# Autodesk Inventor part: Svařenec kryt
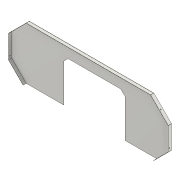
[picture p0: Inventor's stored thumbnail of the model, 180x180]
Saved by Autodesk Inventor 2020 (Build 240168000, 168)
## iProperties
Created: 2025-04
Part Number: Svařenec kryt
Material: Ocel
Document SubType Name: Modeling
Designer: doma
Density: 7.85 g/cm^3
Appearance: Ocel
Mass: 2680.45 g
Surface Area: 5732.74 cm^2
Volume: 341.459 cm^3
Author: doma
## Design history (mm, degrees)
sketch "Náčrt1"
  geometry: L1 (1513.721, 322.322)-(1513.721, 397.322); L2 (1513.721, 322.322)-(1513.721, 247.322); L3 (2563.721, 322.322)-(2563.721, 397.322); L4 (2563.721, 322.322)-(2563.721, 247.322); L5 (1663.721, 152.322)-(1608.721, 152.322); L6 (1663.721, 152.322)-(1853.721, 152.322); L7 (2263.721, 152.322)-(2468.721, 152.322); L8 (2263.721, 322.322)-(2263.721, 255.322); L9 (2233.721, 432.322)-(1883.721, 432.322); L10 (2263.721, 402.322)-(2233.721, 432.322); L11 (2263.721, 322.322)-(2263.721, 402.322); L12 (1853.721, 322.322)-(1853.721, 402.322); L13 (1883.721, 432.322)-(1853.721, 402.322); L14 (1853.721, 322.322)-(1853.721, 152.322); L15 (1513.721, 397.322)-(1628.721, 512.322); L16 (2563.721, 397.322)-(2448.721, 512.322); L17 (1513.721, 247.322)-(1608.721, 152.322); L18 (2563.721, 247.322)-(2468.721, 152.322); L19 (2058.721, 512.322)-(1628.721, 512.322); L20 (2058.721, 512.322)-(2448.721, 512.322); L21 (2263.721, 255.322)-(2263.721, 152.322); L22 (2058.721, 514.322)-(2448.721, 514.322); L23 (2565.135, 398.736)-(2450.135, 513.736); L24 (2565.721, 322.322)-(2565.721, 397.322); L25 (2565.721, 322.322)-(2565.721, 247.322); L26 (2565.135, 245.908)-(2470.135, 150.908); L27 (2263.721, 150.322)-(2468.721, 150.322); L28 (2261.721, 255.322)-(2261.721, 152.322); L29 (2261.721, 322.322)-(2261.721, 255.322); L30 (2261.721, 322.322)-(2261.721, 402.322); L31 (2262.307, 400.908)-(2232.307, 430.908); L32 (2233.721, 430.322)-(1883.721, 430.322); L33 (1885.135, 430.908)-(1855.135, 400.908); L34 (1855.721, 322.322)-(1855.721, 402.322); L35 (1855.721, 322.322)-(1855.721, 152.322); L36 (1663.721, 150.322)-(1853.721, 150.322); L37 (1663.721, 150.322)-(1608.721, 150.322); L38 (1512.307, 245.908)-(1607.307, 150.908); L39 (1511.721, 322.322)-(1511.721, 247.322); L40 (1511.721, 322.322)-(1511.721, 397.322); L41 (1512.307, 398.736)-(1627.307, 513.736); L42 (2058.721, 514.322)-(1628.721, 514.322); L43 (2263.721, 150.322)-(2261.721, 150.322); L44 (2261.721, 150.322)-(2261.721, 152.322); L45 (2470.135, 150.908)-(2469.549, 150.322); L46 (1607.307, 150.908)-(1607.893, 150.322); L47 (1607.893, 150.322)-(1608.721, 150.322); L48 (1853.721, 150.322)-(1855.721, 150.322); L49 (1855.721, 150.322)-(1855.721, 152.322); L50 (1631.284, 519.411)-(1626.458, 514.585); L51 (1626.458, 514.585)-(1511.458, 399.585); L52 (1511.458, 399.585)-(1508.966, 397.092); L53 (1510.521, 322.322)-(1510.521, 397.322); L54 (1510.521, 397.322)-(1510.521, 401.607); L55 (1510.521, 322.322)-(1510.521, 247.322); L56 (1510.521, 247.322)-(1510.521, 242.989); L57 (1507.769, 248.748)-(1511.458, 245.059); L58 (1511.458, 245.059)-(1606.458, 150.059); L59 (1606.458, 150.059)-(1607.044, 149.473); L60 (1607.044, 149.473)-(1607.893, 150.322); L61 (1512.307, 245.908)-(1511.721, 246.494); L62 (1510.521, 247.694)-(1508.618, 249.597); L63 (1511.721, 247.322)-(1511.721, 246.494); L64 (1511.721, 244.796)-(1511.721, 242.989)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; 21 further points
  constraints: 200 end point, 21 parallel, 14 point on line, 8 vertical, 6 horizontal, 3 perpendicular, 1 collinear, 1 other
  dimensions: "d54" = 2 distance between parallel lines of L20 L22; "d55" = 2 distance between parallel lines of L16 L23; "d56" = 2 distance between parallel lines of L3 L24; "d57" = 2 distance between parallel lines of L4 L25; "d58" = 2 distance between parallel lines of L18 L26; "d59" = 2 distance between parallel lines of L7 L27; "d60" = 2 distance between parallel lines of L21 L28; "d61" = 2 distance between parallel lines of L8 L29; "d62" = 2 distance between parallel lines of L11 L30; "d63" = 2 distance between parallel lines of L10 L31; "d64" = 2 distance between parallel lines of L9 L32; "d65" = 2 distance between parallel lines of L13 L33; "d66" = 2 distance between parallel lines of L12 L34; "d67" = 2 distance between parallel lines of L14 L35; "d68" = 2 distance between parallel lines of L6 L36; "d69" = 2 distance between parallel lines of L5 L37; "d70" = 2 distance between parallel lines of L17 L38; "d71" = 2 distance between parallel lines of L2 L39; "d72" = 2 distance between parallel lines of L1 L40; "d73" = 2 distance between parallel lines of L15 L41; "d74" = 2 distance between parallel lines of L19 L42; "d75" = 1.2 distance between parallel lines of L41 L51; "d76" = 1.2 distance between parallel lines of L40 L53; "d77" = 1.2 distance between parallel lines of L39 L55; "d78" = 1.2 distance between parallel lines of L38 L58; "d79" = 1.2 distance between parallel lines of L42 L69; "d80" = 1.2 distance between parallel lines of L22 L71; "d81" = 1.2 distance between parallel lines of L23 L78; "d82" = 1.2 distance between parallel lines of L24 L80; "d83" = 1.2 distance between parallel lines of L25 L82; "d84" = 1.2 distance between parallel lines of L26 L85
extrude "Vysunutí1" new body sketch "Náčrt1" distance "d85" = 21.2; taper "d86" = 0 deg
extrude "Vysunutí2" join sketch "Náčrt1" distance "d87" = 1.2; taper "d88" = 0 deg
sketch "Náčrt2"
  geometry: L1 (-165.286, 21.2)-(0, 21.2) reference; L2 (-165.286, 13.2)-(0, 13.2); C1 r 2.75 at (-82.643, 13.2); 1 further point
  constraints: 2 end point, 1 centre point, 1 midpoint, 1 parallel
  dimensions: "d89" = 8 distance between parallel lines of L1 L2; "d90" = 5.5 diameter of C1
extrude "Vysunutí3" cut sketch "Náčrt2" distance "d91" = 1.2; taper "d92" = 0 deg
sketch "Náčrt3"
  geometry: L1 (-165.286, 21.2)-(0, 21.2) reference; L2 (-165.286, 13.2)-(0, 13.2); C1 r 2.75 at (-82.643, 13.2); 1 further point
  constraints: 2 end point, 1 centre point, 1 midpoint, 1 parallel
  dimensions: "d93" = 8 distance between parallel lines of L1 L2; "d94" = 5.5 diameter of C1
extrude "Vysunutí4" cut sketch "Náčrt3" distance "d95" = 1.2; taper "d96" = 0 deg
sketch "Náčrt4"
  geometry: L1 (21.2, 152.651)-(21.2, 0) reference; L2 (13.2, 152.651)-(13.2, 0); C1 r 2.75 at (13.2, 20); 1 further point
  constraints: 2 end point, 1 centre point, 1 parallel, 1 point on line
  dimensions: "d97" = 8 distance between parallel lines of L1 L2; "d98" = 5.5 diameter of C1; "d99" = 20 vertical distance of L1.end C1.centre
extrude "Vysunutí5" cut sketch "Náčrt4" extent not by distance; stored distance "d100" = 0; taper "d101" = 0 deg
sketch "Náčrt5"
  geometry: L1 (-1627.893, 514.322)-(-2449.549, 514.322) reference; L2 (-1627.893, 514.322)-(-1627.893, 515.522); L3 (-2450.047, 515.522)-(-1627.396, 515.522) reference; L4 (-1627.893, 514.322)-(-1627.044, 515.171); L5 (-1627.396, 515.522)-(-1510.521, 398.647) reference; L6 (-1628.721, 515.522)-(-1624.975, 515.522) reference; L7 (-1631.284, 519.411)-(-1626.458, 514.585) reference; L8 (-1511.721, 398.15)-(-1627.893, 514.322) reference; L9 (-1511.721, 398.15)-(-1510.873, 398.999); L10 (-1511.721, 398.15)-(-1510.521, 398.15); L11 (-1510.521, 398.647)-(-1510.521, 245.996) reference; L12 (-1511.458, 399.585)-(-1508.966, 397.092) reference; L13 (-1510.521, 397.322)-(-1510.521, 401.607) reference; L14 (-1510.521, 247.322)-(-1510.521, 242.989) reference; L15 (-1507.769, 248.748)-(-1511.458, 245.059) reference; L16 (-1511.721, 246.494)-(-1511.721, 398.15) reference; L17 (-1511.721, 246.494)-(-1510.521, 246.494); L18 (-1511.721, 246.494)-(-1510.873, 245.645); L19 (-1510.521, 245.996)-(-1607.044, 149.473) reference; L20 (-1510.521, 245.996)-(-1607.044, 149.473) reference; L21 (-2448.721, 515.522)-(-2452.625, 515.522) reference; L22 (-2448.73, 516.839)-(-2450.984, 514.585) reference; L23 (-2449.549, 514.322)-(-2449.549, 515.522); L24 (-2449.549, 514.322)-(-2450.398, 515.171); L25 (-2565.984, 399.585)-(-2570.969, 394.6) reference; L26 (-2566.921, 397.322)-(-2566.921, 403.132) reference; L27 (-2565.721, 398.15)-(-2565.721, 246.494) reference; L28 (-2565.721, 398.15)-(-2566.57, 398.999); L29 (-2566.921, 398.647)-(-2450.047, 515.522) reference; L30 (-2449.549, 514.322)-(-2565.721, 398.15) reference; L31 (-2565.721, 398.15)-(-2566.921, 398.15); L32 (-2566.921, 245.996)-(-2566.921, 398.647) reference; L33 (-2565.721, 246.494)-(-2469.549, 150.322) reference; L34 (-2565.721, 246.494)-(-2566.921, 246.494); L35 (-2565.721, 246.494)-(-2566.57, 245.645); L36 (-2470.398, 149.473)-(-2566.921, 245.996) reference; L37 (-2470.398, 149.473)-(-2566.921, 245.996) reference; L38 (-2565.984, 245.059)-(-2568.811, 247.887) reference; 7 further points
  constraints: 24 end point, 12 point on line, 8 perpendicular, 1 horizontal, 1 vertical
extrude "Vysunutí6" cut sketch "Náčrt5" extent not by distance; stored distance "d102" = 0; taper "d103" = 0 deg
node "Těleso1"
